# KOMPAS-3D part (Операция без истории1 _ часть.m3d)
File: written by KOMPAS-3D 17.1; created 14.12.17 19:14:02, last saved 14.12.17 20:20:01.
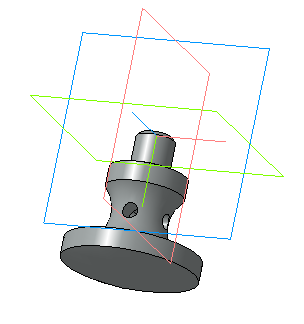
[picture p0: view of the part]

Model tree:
1. Операция без истории:1  (with: Сечение модели:1)

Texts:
  Точка начала. Х
  Точка начала. Y
  Точка начала. Z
